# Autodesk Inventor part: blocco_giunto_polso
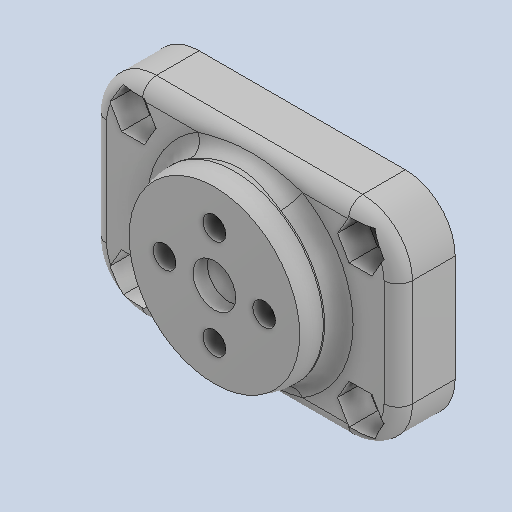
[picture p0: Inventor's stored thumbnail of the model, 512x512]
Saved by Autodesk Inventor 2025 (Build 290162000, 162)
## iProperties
Created: 2025-06
Part Number: blocco_giunto_polso
Material: Generico
Document SubType Name: Modeling
Designer: Ryzen5700u
Density: 1 g/cm^3
Appearance: Default
Author: Ryzen5700u
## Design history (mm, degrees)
feature "Solido1"
node "Solido2"
